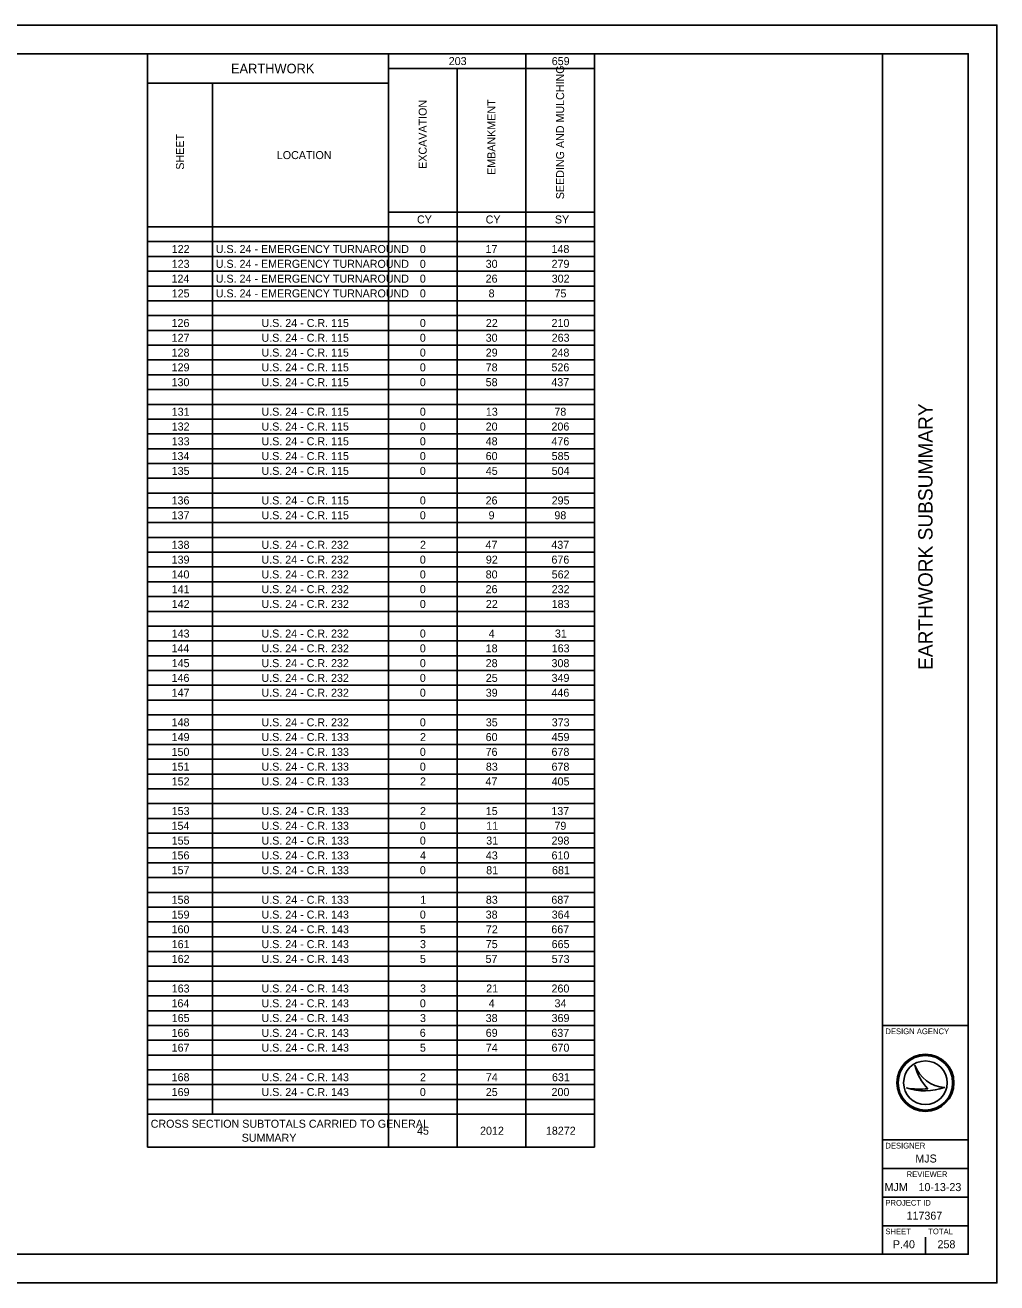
# Model space of a CAD drawing. Extents: x 0 to 34, y 0 to 22.
# Drawn here: x 17 to 34, y 0 to 22 of the extents above; entities that cross this region are included whole.
import ezdxf

# ---------------------------------------------------------------- set-up
doc = ezdxf.new("R2010")
doc.units = 0
for name, color, linetype in [('Default', 7, 'Continuous'), ('SH_Border', 7, 'Continuous'), ('SH_Cut_Line', 7, 'Continuous'), ('SH_Data', 7, 'Continuous')]:
    doc.layers.add(name, color=color, linetype=linetype)

msp = doc.modelspace()

# ---------------------------------------------------------------- linework, layer by layer
at = {"layer": 'Default'}
for p, q in [((19.139, 21.5), (26.96, 21.5)), ((19.139, 21.5), (19.139, 2.372)), ((23.354, 21.5), (23.354, 2.372)), ((25.758, 21.5), (25.758, 2.372)), ((26.96, 21.5), (26.96, 2.372)), ((23.354, 21.241), (26.96, 21.241)), ((24.556, 21.241), (24.556, 2.372)), ((19.139, 20.983), (23.354, 20.983)), ((20.28, 20.983), (20.28, 2.95)), ((23.354, 18.73), (26.96, 18.73)), ((19.139, 18.472), (26.96, 18.472)), ((19.139, 18.213), (26.96, 18.213)), ((19.139, 17.954), (26.96, 17.954)), ((19.139, 17.696), (26.96, 17.696)), ((19.139, 17.437), (26.96, 17.437)), ((19.139, 17.178), (26.96, 17.178)), ((19.139, 16.92), (26.96, 16.92)), ((19.139, 16.661), (26.96, 16.661)), ((19.139, 16.402), (26.96, 16.402)), ((19.139, 16.143), (26.96, 16.143)), ((19.139, 15.885), (26.96, 15.885)), ((19.139, 15.626), (26.96, 15.626)), ((19.139, 15.367), (26.96, 15.367)), ((19.139, 15.109), (26.96, 15.109)), ((19.139, 14.85), (26.96, 14.85)), ((19.139, 14.591), (26.96, 14.591)), ((19.139, 14.333), (26.96, 14.333)), ((19.139, 14.074), (26.96, 14.074)), ((19.139, 13.815), (26.96, 13.815)), ((19.139, 13.557), (26.96, 13.557)), ((19.139, 13.298), (26.96, 13.298)), ((19.139, 13.039), (26.96, 13.039)), ((19.139, 12.78), (26.96, 12.78)), ((19.139, 12.522), (26.96, 12.522)), ((19.139, 12.263), (26.96, 12.263)), ((19.139, 12.004), (26.96, 12.004)), ((19.139, 11.746), (26.96, 11.746)), ((19.139, 11.487), (26.96, 11.487)), ((19.139, 11.228), (26.96, 11.228)), ((19.139, 10.97), (26.96, 10.97)), ((19.139, 10.711), (26.96, 10.711)), ((19.139, 10.452), (26.96, 10.452)), ((19.139, 10.193), (26.96, 10.193)), ((19.139, 9.935), (26.96, 9.935)), ((19.139, 9.676), (26.96, 9.676)), ((19.139, 9.417), (26.96, 9.417)), ((19.139, 9.159), (26.96, 9.159)), ((19.139, 8.9), (26.96, 8.9)), ((19.139, 8.641), (26.96, 8.641)), ((19.139, 8.383), (26.96, 8.383)), ((19.139, 8.124), (26.96, 8.124)), ((19.139, 7.865), (26.96, 7.865)), ((19.139, 7.607), (26.96, 7.607)), ((19.139, 7.348), (26.96, 7.348)), ((19.139, 7.089), (26.96, 7.089)), ((19.139, 6.83), (26.96, 6.83)), ((19.139, 6.572), (26.96, 6.572)), ((19.139, 6.313), (26.96, 6.313)), ((19.139, 6.054), (26.96, 6.054)), ((19.139, 5.796), (26.96, 5.796)), ((19.139, 5.537), (26.96, 5.537)), ((19.139, 5.278), (26.96, 5.278)), ((19.139, 5.02), (26.96, 5.02)), ((19.139, 4.761), (26.96, 4.761)), ((19.139, 4.502), (26.96, 4.502)), ((19.139, 4.243), (26.96, 4.243)), ((19.139, 3.985), (26.96, 3.985)), ((19.139, 3.726), (26.96, 3.726)), ((19.139, 3.467), (26.96, 3.467)), ((19.139, 3.209), (26.96, 3.209)), ((19.139, 2.95), (26.96, 2.95)), ((19.139, 2.372), (26.96, 2.372))]:
    msp.add_line(p, q, dxfattribs=at)
at = {"layer": 'SH_Border'}
for p, q in [((32, 0.5), (32, 21.5)), ((32, 4.5), (33.5, 4.5)), ((32, 2.5), (33.5, 2.5)), ((32, 2), (33.5, 2)), ((32, 1.5), (33.5, 1.5)), ((32, 1), (33.5, 1))]:
    msp.add_line(p, q, dxfattribs=at)
msp.add_lwpolyline([(1.5, 21.5), (33.5, 21.5), (33.5, 0.5), (1.5, 0.5)], close=True, dxfattribs=at)
at = {"layer": 'SH_Cut_Line'}
msp.add_lwpolyline([(0, 0), (34, 0), (34, 22), (0, 22)], close=True, dxfattribs=at)
at = {"layer": 'SH_Data'}
for p, q in [((32.567, 3.81), (32.567, 3.81)), ((32.417, 3.41), (32.417, 3.41)), ((32.75, 3.5), (32.75, 3.5)), ((33.087, 3.419), (33.087, 3.419)), ((32.375, 0.675), (32.375, 0.675)), ((32.75, 0.5), (32.75, 0.8))]:
    msp.add_line(p, q, dxfattribs=at)
for radius in [0.5, 0.477, 0.477, 0.382]:
    msp.add_circle((32.75, 3.5), radius, dxfattribs=at)
for centre, radius, start, end in [((33.116, 3.998), 0.58, 198.9257, 198.9319), ((33.347, 3.97), 0.796, 191.6379, 191.6421), ((33.116, 3.998), 0.58, 198.9319, 267.1657), ((33.347, 3.97), 0.796, 191.6421, 226.0947), ((32.739, 4.37), 1.013, 251.4576, 290.0832), ((32.648, 4.654), 1.266, 259.4964, 259.4995), ((32.739, 4.37), 1.013, 251.4527, 251.4576), ((32.648, 4.654), 1.266, 259.4995, 276.6672)]:
    msp.add_arc(centre, radius, start, end, dxfattribs=at)

# ---------------------------------------------------------------- texts
at = {"layer": 'Default'}
for s, height, p in [('203', 0.14, (24.411, 21.302)), ('659', 0.14, (26.213, 21.301)), ('EARTHWORK', 0.168, (20.6, 21.157)), ('LOCATION', 0.14, (21.403, 19.657)), ('CY', 0.14, (23.855, 18.531)), ('CY', 0.14, (25.057, 18.531)), ('SY', 0.14, (26.268, 18.531)), ('122', 0.14, (19.564, 18.014)), ('U.S. 24 - EMERGENCY TURNAROUND', 0.14, (20.335, 18.014)), ('0', 0.14, (23.905, 18.014)), ('17', 0.14, (25.054, 18.014)), ('148', 0.14, (26.209, 18.014)), ('123', 0.14, (19.564, 17.755)), ('U.S. 24 - EMERGENCY TURNAROUND', 0.14, (20.335, 17.755)), ('0', 0.14, (23.905, 17.755)), ('30', 0.14, (25.057, 17.755)), ('279', 0.14, (26.21, 17.755)), ('124', 0.14, (19.561, 17.496)), ('U.S. 24 - EMERGENCY TURNAROUND', 0.14, (20.335, 17.496)), ('0', 0.14, (23.905, 17.496)), ('26', 0.14, (25.056, 17.496)), ('302', 0.14, (26.212, 17.496)), ('125', 0.14, (19.564, 17.238)), ('U.S. 24 - EMERGENCY TURNAROUND', 0.14, (20.335, 17.238)), ('0', 0.14, (23.905, 17.238)), ('8', 0.14, (25.108, 17.238)), ('75', 0.14, (26.261, 17.238)), ('126', 0.14, (19.562, 16.72)), ('U.S. 24 - C.R. 115', 0.14, (21.135, 16.72)), ('0', 0.14, (23.905, 16.72)), ('22', 0.14, (25.06, 16.72)), ('210', 0.14, (26.209, 16.72)), ('127', 0.14, (19.563, 16.462)), ('U.S. 24 - C.R. 115', 0.14, (21.135, 16.462)), ('0', 0.14, (23.905, 16.462)), ('30', 0.14, (25.057, 16.462)), ('263', 0.14, (26.212, 16.462)), ('128', 0.14, (19.563, 16.203)), ('U.S. 24 - C.R. 115', 0.14, (21.135, 16.203)), ('0', 0.14, (23.905, 16.203)), ('29', 0.14, (25.058, 16.203)), ('248', 0.14, (26.209, 16.203)), ('129', 0.14, (19.563, 15.944)), ('U.S. 24 - C.R. 115', 0.14, (21.135, 15.944)), ('0', 0.14, (23.905, 15.944)), ('78', 0.14, (25.057, 15.944)), ('526', 0.14, (26.208, 15.944)), ('130', 0.14, (19.562, 15.685)), ('U.S. 24 - C.R. 115', 0.14, (21.135, 15.685)), ('0', 0.14, (23.905, 15.685)), ('58', 0.14, (25.057, 15.685)), ('437', 0.14, (26.206, 15.685)), ('131', 0.14, (19.564, 15.168)), ('U.S. 24 - C.R. 115', 0.14, (21.135, 15.168)), ('0', 0.14, (23.905, 15.168)), ('13', 0.14, (25.06, 15.168)), ('78', 0.14, (26.259, 15.168)), ('132', 0.14, (19.564, 14.909)), ('U.S. 24 - C.R. 115', 0.14, (21.135, 14.909)), ('0', 0.14, (23.905, 14.909)), ('20', 0.14, (25.057, 14.909)), ('206', 0.14, (26.208, 14.909)), ('133', 0.14, (19.564, 14.651)), ('U.S. 24 - C.R. 115', 0.14, (21.135, 14.651)), ('0', 0.14, (23.905, 14.651)), ('48', 0.14, (25.057, 14.651)), ('476', 0.14, (26.208, 14.651)), ('134', 0.14, (19.561, 14.392)), ('U.S. 24 - C.R. 115', 0.14, (21.135, 14.392)), ('0', 0.14, (23.905, 14.392)), ('60', 0.14, (25.057, 14.392)), ('585', 0.14, (26.211, 14.392)), ('135', 0.14, (19.564, 14.133)), ('U.S. 24 - C.R. 115', 0.14, (21.135, 14.133)), ('0', 0.14, (23.905, 14.133)), ('45', 0.14, (25.059, 14.133)), ('504', 0.14, (26.212, 14.133)), ('136', 0.14, (19.562, 13.616)), ('U.S. 24 - C.R. 115', 0.14, (21.135, 13.616)), ('0', 0.14, (23.905, 13.616)), ('26', 0.14, (25.056, 13.616)), ('295', 0.14, (26.211, 13.616)), ('137', 0.14, (19.563, 13.357)), ('U.S. 24 - C.R. 115', 0.14, (21.135, 13.357)), ('0', 0.14, (23.905, 13.357)), ('9', 0.14, (25.108, 13.357)), ('98', 0.14, (26.259, 13.357)), ('138', 0.14, (19.563, 12.84)), ('U.S. 24 - C.R. 232', 0.14, (21.134, 12.84)), ('2', 0.14, (23.908, 12.84)), ('437', 0.14, (26.206, 12.84)), ('47', 0.14, (25.054, 12.84)), ('139', 0.14, (19.563, 12.581)), ('U.S. 24 - C.R. 232', 0.14, (21.134, 12.581)), ('0', 0.14, (23.905, 12.581)), ('92', 0.14, (25.06, 12.581)), ('676', 0.14, (26.208, 12.581)), ('140', 0.14, (19.562, 12.322)), ('U.S. 24 - C.R. 232', 0.14, (21.134, 12.322)), ('0', 0.14, (23.905, 12.322)), ('80', 0.14, (25.057, 12.322)), ('562', 0.14, (26.212, 12.322)), ('141', 0.14, (19.564, 12.064)), ('U.S. 24 - C.R. 232', 0.14, (21.134, 12.064)), ('0', 0.14, (23.905, 12.064)), ('26', 0.14, (25.056, 12.064)), ('232', 0.14, (26.212, 12.064)), ('142', 0.14, (19.564, 11.805)), ('U.S. 24 - C.R. 232', 0.14, (21.134, 11.805)), ('0', 0.14, (23.905, 11.805)), ('22', 0.14, (25.06, 11.805)), ('183', 0.14, (26.212, 11.805)), ('143', 0.14, (19.564, 11.288)), ('U.S. 24 - C.R. 232', 0.14, (21.134, 11.288)), ('0', 0.14, (23.905, 11.288)), ('4', 0.14, (25.11, 11.288)), ('31', 0.14, (26.268, 11.288)), ('144', 0.14, (19.561, 11.029)), ('U.S. 24 - C.R. 232', 0.14, (21.134, 11.029)), ('0', 0.14, (23.905, 11.029)), ('18', 0.14, (25.057, 11.029)), ('163', 0.14, (26.212, 11.029)), ('145', 0.14, (19.564, 10.77)), ('U.S. 24 - C.R. 232', 0.14, (21.134, 10.77)), ('0', 0.14, (23.905, 10.77)), ('28', 0.14, (25.057, 10.77)), ('308', 0.14, (26.209, 10.77)), ('146', 0.14, (19.562, 10.512)), ('U.S. 24 - C.R. 232', 0.14, (21.134, 10.512)), ('0', 0.14, (23.905, 10.512)), ('25', 0.14, (25.059, 10.512)), ('349', 0.14, (26.21, 10.512)), ('147', 0.14, (19.563, 10.253)), ('U.S. 24 - C.R. 232', 0.14, (21.134, 10.253)), ('0', 0.14, (23.905, 10.253)), ('39', 0.14, (25.058, 10.253)), ('446', 0.14, (26.208, 10.253)), ('148', 0.14, (19.563, 9.735)), ('U.S. 24 - C.R. 232', 0.14, (21.134, 9.735)), ('0', 0.14, (23.905, 9.735)), ('35', 0.14, (25.059, 9.735)), ('373', 0.14, (26.212, 9.735)), ('149', 0.14, (19.563, 9.477)), ('U.S. 24 - C.R. 133', 0.14, (21.135, 9.477)), ('2', 0.14, (23.908, 9.477)), ('60', 0.14, (25.057, 9.477)), ('459', 0.14, (26.21, 9.477)), ('150', 0.14, (19.562, 9.218)), ('U.S. 24 - C.R. 133', 0.14, (21.135, 9.218)), ('0', 0.14, (23.905, 9.218)), ('76', 0.14, (25.056, 9.218)), ('678', 0.14, (26.209, 9.218)), ('151', 0.14, (19.564, 8.959)), ('U.S. 24 - C.R. 133', 0.14, (21.135, 8.959)), ('0', 0.14, (23.905, 8.959)), ('83', 0.14, (25.06, 8.959)), ('678', 0.14, (26.209, 8.959)), ('152', 0.14, (19.564, 8.701)), ('U.S. 24 - C.R. 133', 0.14, (21.135, 8.701)), ('2', 0.14, (23.908, 8.701)), ('47', 0.14, (25.054, 8.701)), ('405', 0.14, (26.211, 8.701)), ('153', 0.14, (19.564, 8.183)), ('U.S. 24 - C.R. 133', 0.14, (21.135, 8.183)), ('2', 0.14, (23.908, 8.183)), ('15', 0.14, (25.059, 8.183)), ('137', 0.14, (26.206, 8.183)), ('154', 0.14, (19.561, 7.925)), ('U.S. 24 - C.R. 133', 0.14, (21.135, 7.925)), ('0', 0.14, (23.905, 7.925)), ('11', 0.14, (25.066, 7.925)), ('79', 0.14, (26.26, 7.925)), ('155', 0.14, (19.564, 7.666)), ('U.S. 24 - C.R. 133', 0.14, (21.135, 7.666)), ('0', 0.14, (23.905, 7.666)), ('31', 0.14, (25.066, 7.666)), ('298', 0.14, (26.209, 7.666)), ('156', 0.14, (19.562, 7.407)), ('U.S. 24 - C.R. 133', 0.14, (21.135, 7.407)), ('4', 0.14, (23.908, 7.407)), ('43', 0.14, (25.06, 7.407)), ('610', 0.14, (26.209, 7.407)), ('157', 0.14, (19.563, 7.148)), ('U.S. 24 - C.R. 133', 0.14, (21.135, 7.148)), ('0', 0.14, (23.905, 7.148)), ('81', 0.14, (25.066, 7.148)), ('681', 0.14, (26.217, 7.148)), ('158', 0.14, (19.563, 6.631)), ('U.S. 24 - C.R. 133', 0.14, (21.135, 6.631)), ('1', 0.14, (23.914, 6.631)), ('83', 0.14, (25.06, 6.631)), ('687', 0.14, (26.206, 6.631)), ('159', 0.14, (19.563, 6.372)), ('U.S. 24 - C.R. 143', 0.14, (21.135, 6.372)), ('0', 0.14, (23.905, 6.372)), ('38', 0.14, (25.057, 6.372)), ('364', 0.14, (26.212, 6.372)), ('160', 0.14, (19.562, 6.114)), ('U.S. 24 - C.R. 143', 0.14, (21.135, 6.114)), ('5', 0.14, (23.907, 6.114)), ('72', 0.14, (25.06, 6.114)), ('667', 0.14, (26.206, 6.114)), ('161', 0.14, (19.564, 5.855)), ('U.S. 24 - C.R. 143', 0.14, (21.135, 5.855)), ('3', 0.14, (23.908, 5.855)), ('75', 0.14, (25.059, 5.855)), ('665', 0.14, (26.211, 5.855)), ('162', 0.14, (19.564, 5.596)), ('U.S. 24 - C.R. 143', 0.14, (21.135, 5.596)), ('5', 0.14, (23.907, 5.596)), ('57', 0.14, (25.054, 5.596)), ('573', 0.14, (26.212, 5.596)), ('163', 0.14, (19.564, 5.079)), ('U.S. 24 - C.R. 143', 0.14, (21.135, 5.079)), ('3', 0.14, (23.908, 5.079)), ('21', 0.14, (25.066, 5.079)), ('260', 0.14, (26.209, 5.079)), ('164', 0.14, (19.561, 4.82)), ('U.S. 24 - C.R. 143', 0.14, (21.135, 4.82)), ('0', 0.14, (23.905, 4.82)), ('4', 0.14, (25.11, 4.82)), ('34', 0.14, (26.262, 4.82)), ('165', 0.14, (19.564, 4.562)), ('U.S. 24 - C.R. 143', 0.14, (21.135, 4.562)), ('3', 0.14, (23.908, 4.562)), ('38', 0.14, (25.057, 4.562)), ('369', 0.14, (26.21, 4.562)), ('166', 0.14, (19.562, 4.303)), ('U.S. 24 - C.R. 143', 0.14, (21.135, 4.303)), ('6', 0.14, (23.904, 4.303)), ('69', 0.14, (25.058, 4.303)), ('637', 0.14, (26.206, 4.303)), ('167', 0.14, (19.563, 4.044)), ('U.S. 24 - C.R. 143', 0.14, (21.135, 4.044)), ('5', 0.14, (23.907, 4.044)), ('74', 0.14, (25.06, 4.044)), ('670', 0.14, (26.209, 4.044)), ('168', 0.14, (19.563, 3.527)), ('U.S. 24 - C.R. 143', 0.14, (21.135, 3.527)), ('2', 0.14, (23.908, 3.527)), ('74', 0.14, (25.06, 3.527)), ('631', 0.14, (26.217, 3.527)), ('169', 0.14, (19.563, 3.268)), ('U.S. 24 - C.R. 143', 0.14, (21.135, 3.268)), ('0', 0.14, (23.905, 3.268)), ('25', 0.14, (25.059, 3.268)), ('200', 0.14, (26.209, 3.268)), ('CROSS SECTION SUBTOTALS CARRIED TO GENERAL ', 0.14, (19.196, 2.713)), ('45', 0.14, (23.856, 2.591)), ('2012', 0.14, (24.959, 2.591)), ('18272', 0.14, (26.111, 2.591)), ('SUMMARY', 0.14, (20.789, 2.468))]:
    msp.add_text(s, height=height, dxfattribs=at).set_placement(p)
for s, p in [('SEEDING AND MULCHING', (26.429, 18.955)), ('EMBANKMENT', (25.227, 19.381)), ('EXCAVATION', (24.025, 19.486)), ('SHEET', (19.779, 19.472))]:
    msp.add_text(s, height=0.14, rotation=90, dxfattribs=at).set_placement(p)
at = {"layer": 'SH_Data'}
msp.add_text('EARTHWORK SUBSUMMARY', height=0.25, rotation=90, dxfattribs=at).set_placement((32.875, 10.722))
for s, height, p in [('DESIGN AGENCY', 0.1, (32.05, 4.35)), ('DESIGNER', 0.1, (32.05, 2.35)), ('MJS', 0.14, (32.574, 2.105)), ('REVIEWER', 0.1, (32.422, 1.85)), ('MJM', 0.14, (32.035, 1.605)), ('10-13-23', 0.14, (32.629, 1.605)), ('PROJECT ID', 0.1, (32.05, 1.35)), ('117367', 0.14, (32.42, 1.105)), ('SHEET', 0.1, (32.05, 0.85)), ('TOTAL', 0.1, (32.8, 0.85)), ('P.40', 0.14, (32.182, 0.605)), ('258', 0.14, (32.962, 0.605))]:
    msp.add_text(s, height=height, dxfattribs=at).set_placement(p)

doc.saveas('drawing.dxf')
